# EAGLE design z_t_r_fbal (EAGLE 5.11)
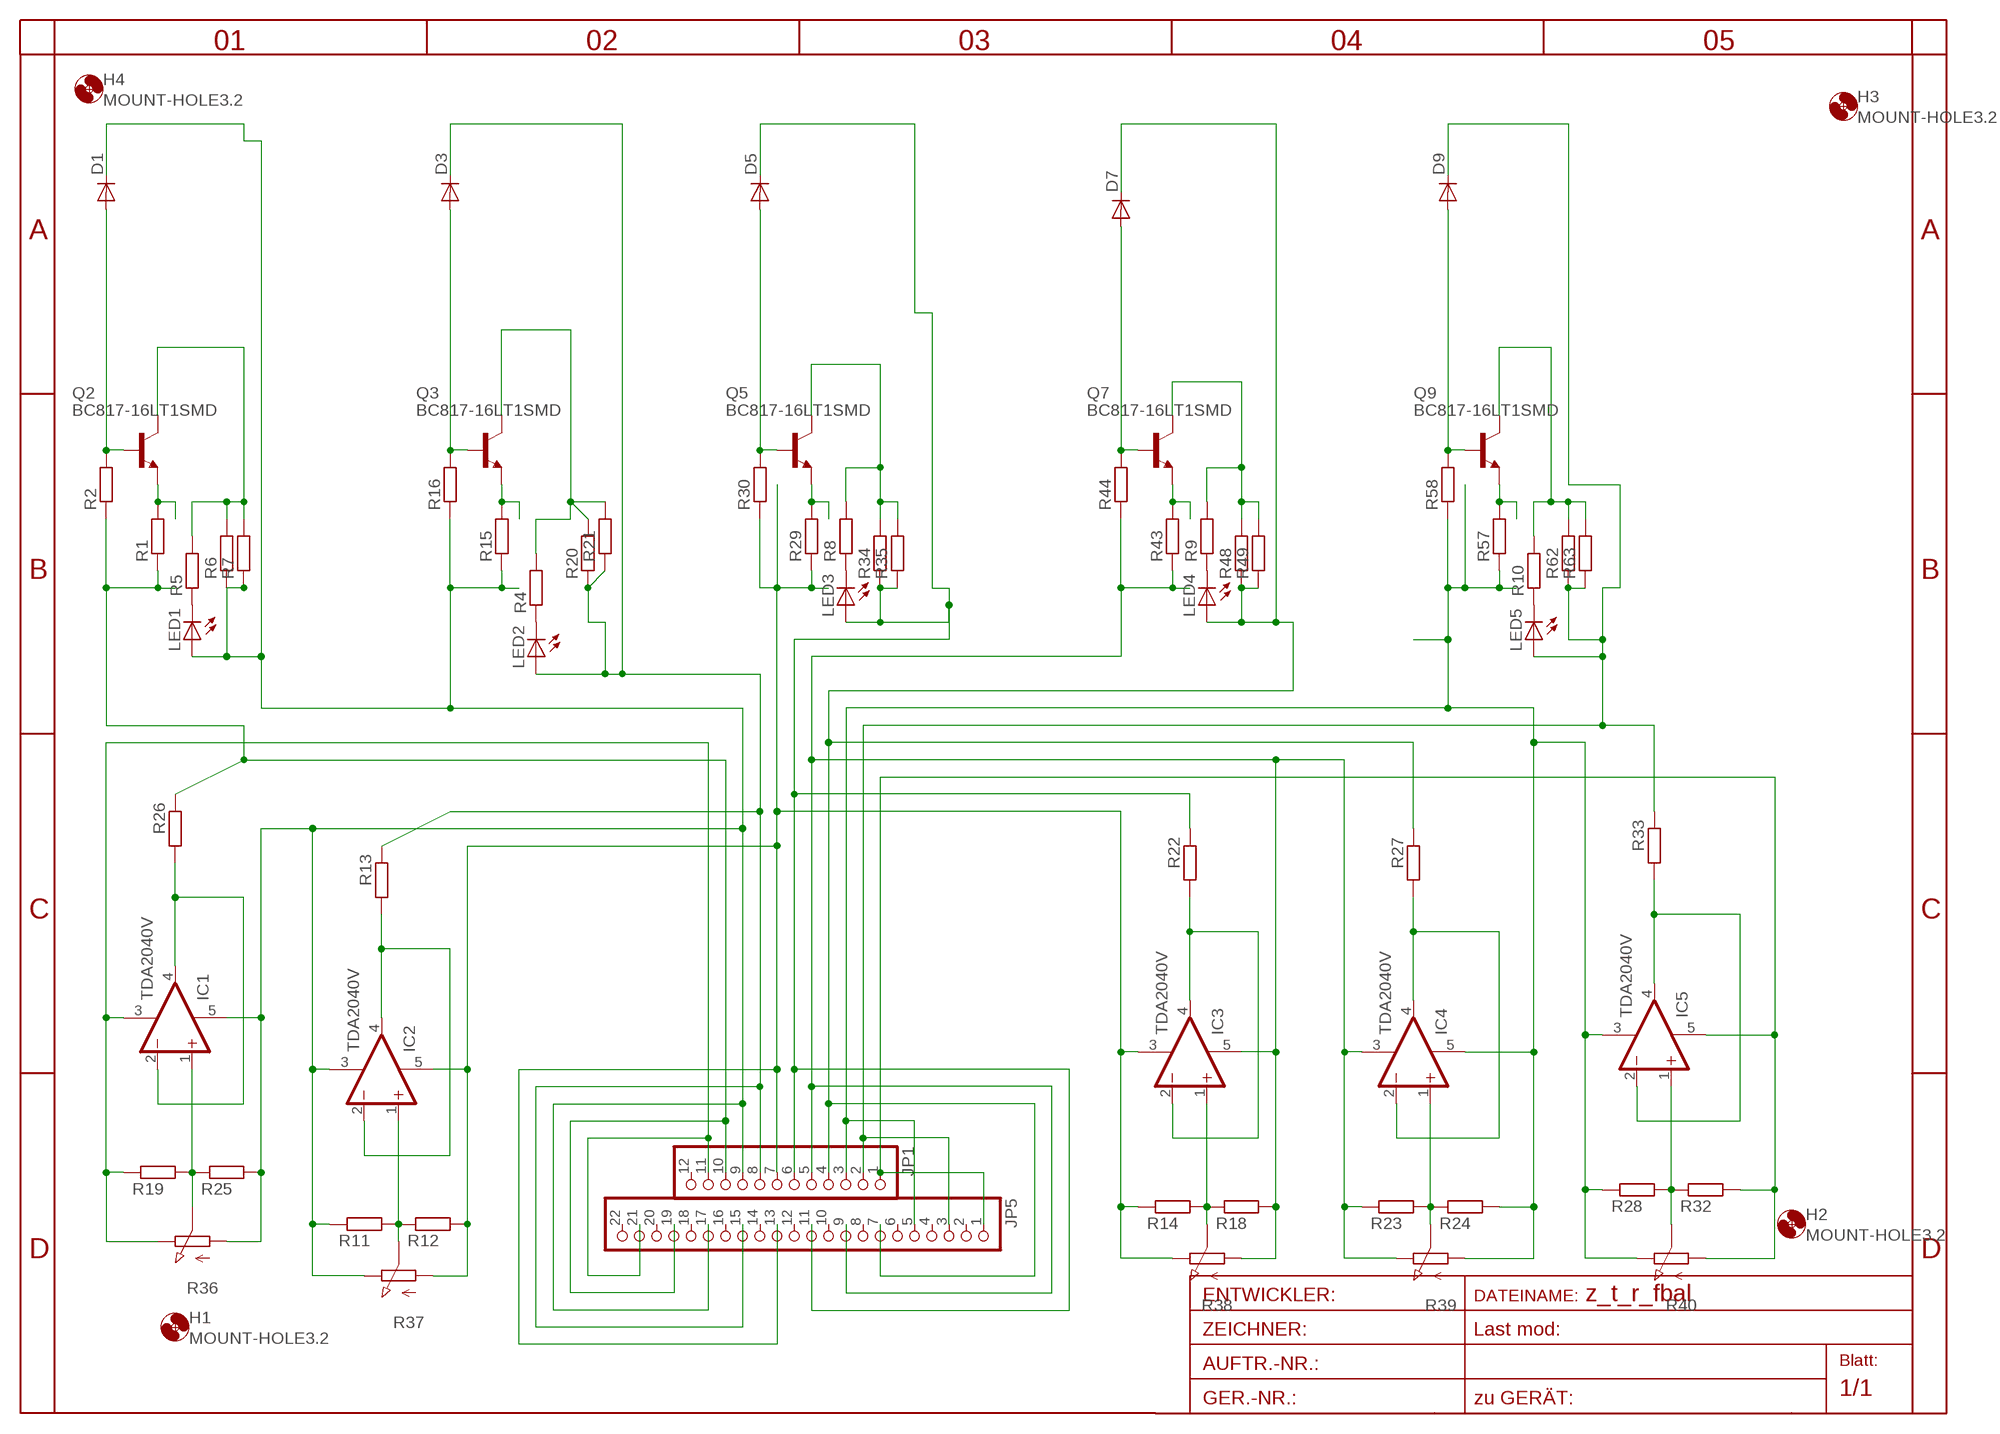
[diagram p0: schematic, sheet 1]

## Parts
D1  DIODE-MINIMELF  [MINIMELF]
D3  DIODE-MINIMELF  [MINIMELF]
D5  DIODE-MINIMELF  [MINIMELF]
D7  DIODE-MINIMELF  [MINIMELF]
D9  DIODE-MINIMELF  [MINIMELF]
H1  MOUNT-HOLE3.2  [3,2]
H2  MOUNT-HOLE3.2  [3,2]
H3  MOUNT-HOLE3.2  [3,2]
H4  MOUNT-HOLE3.2  [3,2]
IC1  TDA2040V  [CB360]
IC2  TDA2040V  [CB360]
IC3  TDA2040V  [CB360]
IC4  TDA2040V  [CB360]
IC5  TDA2040V  [CB360]
JP1  PINHD-1X12  [1X12]
JP5  PINHD-1X22  [1X22]
LED1  LEDCHIPLED_1206  [CHIPLED_1206]
LED2  LEDCHIPLED_1206  [CHIPLED_1206]
LED3  LEDCHIPLED_1206  [CHIPLED_1206]
LED4  LEDCHIPLED_1206  [CHIPLED_1206]
LED5  LEDCHIPLED_1206  [CHIPLED_1206]
Q2  BC817-16LT1SMD  [SOT23-BEC]
Q3  BC817-16LT1SMD  [SOT23-BEC]
Q5  BC817-16LT1SMD  [SOT23-BEC]
Q7  BC817-16LT1SMD  [SOT23-BEC]
Q9  BC817-16LT1SMD  [SOT23-BEC]
R1  R-EU_R1206  [R1206]
R2  R-EU_R0805  [R0805]
R4  R-EU_R1206  [R1206]
R5  R-EU_R1206  [R1206]
R6  R-EU_R3225  [R3225]
R7  R-EU_R3225  [R3225]
R8  R-EU_R1206  [R1206]
R9  R-EU_R1206  [R1206]
R10  R-EU_R1206  [R1206]
R11  R-EU_0204/5  [0204/5]
R12  R-EU_0204/5  [0204/5]
R13  R-EU_0309/10  [0309/10]
R14  R-EU_0204/5  [0204/5]
R15  R-EU_R1206  [R1206]
R16  R-EU_R0805  [R0805]
R18  R-EU_0204/5  [0204/5]
R19  R-EU_0204/5  [0204/5]
R20  R-EU_R3225  [R3225]
R21  R-EU_R3225  [R3225]
R22  R-EU_0309/10  [0309/10]
R23  R-EU_0204/5  [0204/5]
R24  R-EU_0204/5  [0204/5]
R25  R-EU_0204/5  [0204/5]
R26  R-EU_0309/10  [0309/10]
R27  R-EU_0309/10  [0309/10]
R28  R-EU_0204/5  [0204/5]
R29  R-EU_R1206  [R1206]
R30  R-EU_R0805  [R0805]
R32  R-EU_0204/5  [0204/5]
R33  R-EU_0309/10  [0309/10]
R34  R-EU_R3225  [R3225]
R35  R-EU_R3225  [R3225]
R36  PC25  [PC25]
R37  PC25  [PC25]
R38  PC25  [PC25]
R39  PC25  [PC25]
R40  PC25  [PC25]
R43  R-EU_R1206  [R1206]
R44  R-EU_R0805  [R0805]
R48  R-EU_R3225  [R3225]
R49  R-EU_R3225  [R3225]
R57  R-EU_R1206  [R1206]
R58  R-EU_R0805  [R0805]
R62  R-EU_R3225  [R3225]
R63  R-EU_R3225  [R3225]

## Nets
B1: JP1.10 JP5.19 R1.1 R2.1 R26.1
B2: D1.C IC1.5(V+) IC2.3(V-) JP1.9 JP5.17 LED1.A R6.1 R7.1 R11.1 R15.1 R16.1 R25.2 R36.A R37.E
B3: D3.C JP1.8 JP5.15 LED2.A R13.1 R20.1 R21.1
B4: IC2.5(V+) IC3.3(V-) JP1.7 JP5.13 R12.2 R14.1 R29.1 R30.1 R37.A R38.E
B5: D5.C JP1.6 JP5.11 LED3.A R22.1 R34.1 R35.1
B6: IC3.5(V+) IC4.3(V-) JP1.5 JP5.9 R18.2 R23.1 R38.A R39.E R43.1 R44.1
B7: D7.C JP1.4 JP5.7 LED4.A R27.1 R48.1 R49.1
B8: IC4.5(V+) IC5.3(V-) JP1.3 JP5.5 R24.2 R28.1 R39.A R40.E R57.1 R58.1
B9: D9.C JP1.2 JP5.3 LED5.A R33.1 R62.1 R63.1
B10: IC5.5(V+) JP1.1 JP5.1 R32.2 R40.A
B-: IC1.3(V-) JP1.11 JP5.21 R19.1 R36.E
D0: D1.A Q2.B R2.2
D2: D3.A Q3.B R16.2
D4: D5.A Q5.B R30.2
D6: D7.A Q7.B R44.2
D8: D9.A Q9.B R58.2
INV_1: IC1.2(-IN) IC1.4(OUT) R26.2
INV_2: IC2.2(-IN) IC2.4(OUT) R13.2
INV_3: IC3.2(-IN) IC3.4(OUT) R22.2
INV_4: IC4.2(-IN) IC4.4(OUT) R27.2
INV_5: IC5.2(-IN) IC5.4(OUT) R33.2
N$1: Q2.C R5.2 R6.2 R7.2
N$2: Q2.E R1.2
N$3: Q3.C R4.2 R20.2 R21.2
N$4: LED2.C R4.1
N$7: Q5.C R8.2 R34.2 R35.2
N$8: LED3.C R8.1
N$9: Q7.C R9.2 R48.2 R49.2
N$11: LED4.C R9.1
N$13: Q9.C R10.2 R62.2 R63.2
N$14: Q7.E R43.2
N$15: LED5.C R10.1
N$17: LED1.C R5.1
N$18: Q9.E R57.2
N$23: Q5.E R29.2
N$24: Q3.E R15.2
NON_I1: IC1.1(+IN) R19.2 R25.1 R36.S
NON_I2: IC2.1(+IN) R11.2 R12.1 R37.S
NON_I3: IC3.1(+IN) R14.2 R18.1 R38.S
NON_I4: IC4.1(+IN) R23.2 R24.1 R39.S
NON_I5: IC5.1(+IN) R28.2 R32.1 R40.S
Unconnected: JP1.12 JP5.2 JP5.4 JP5.6 JP5.8 JP5.10 JP5.12 JP5.14 JP5.16 JP5.18 JP5.20 JP5.22

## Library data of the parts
D1 D3 D5 D7 D9 = diode-1:DIODE-: DIODE
H1-H4 = holes:MOUNT-HOLE: MOUNTING HOLE with drill center marker
IC1-IC5 = linear:TDA2040: Power OP AMP
JP1 = pinhead:PINHD-1X12: PIN HEADER
JP5 = pinhead:PINHD-1X22: PIN HEADER
LED1-LED5 = led:LED: LED
Q2 Q3 Q5 Q7 Q9 = transistor-npn:BC817*: NPN Transistor
R1 R2 R4-R16 R18-R30 R32-R35 R43 R44 R48 R49 R57 R58 R62 R63 = rcl-2:R-EU_: RESISTOR, European symbol
R36-R40 = pot-vitrohm:PC25: VITROHM POTENTIOMETER

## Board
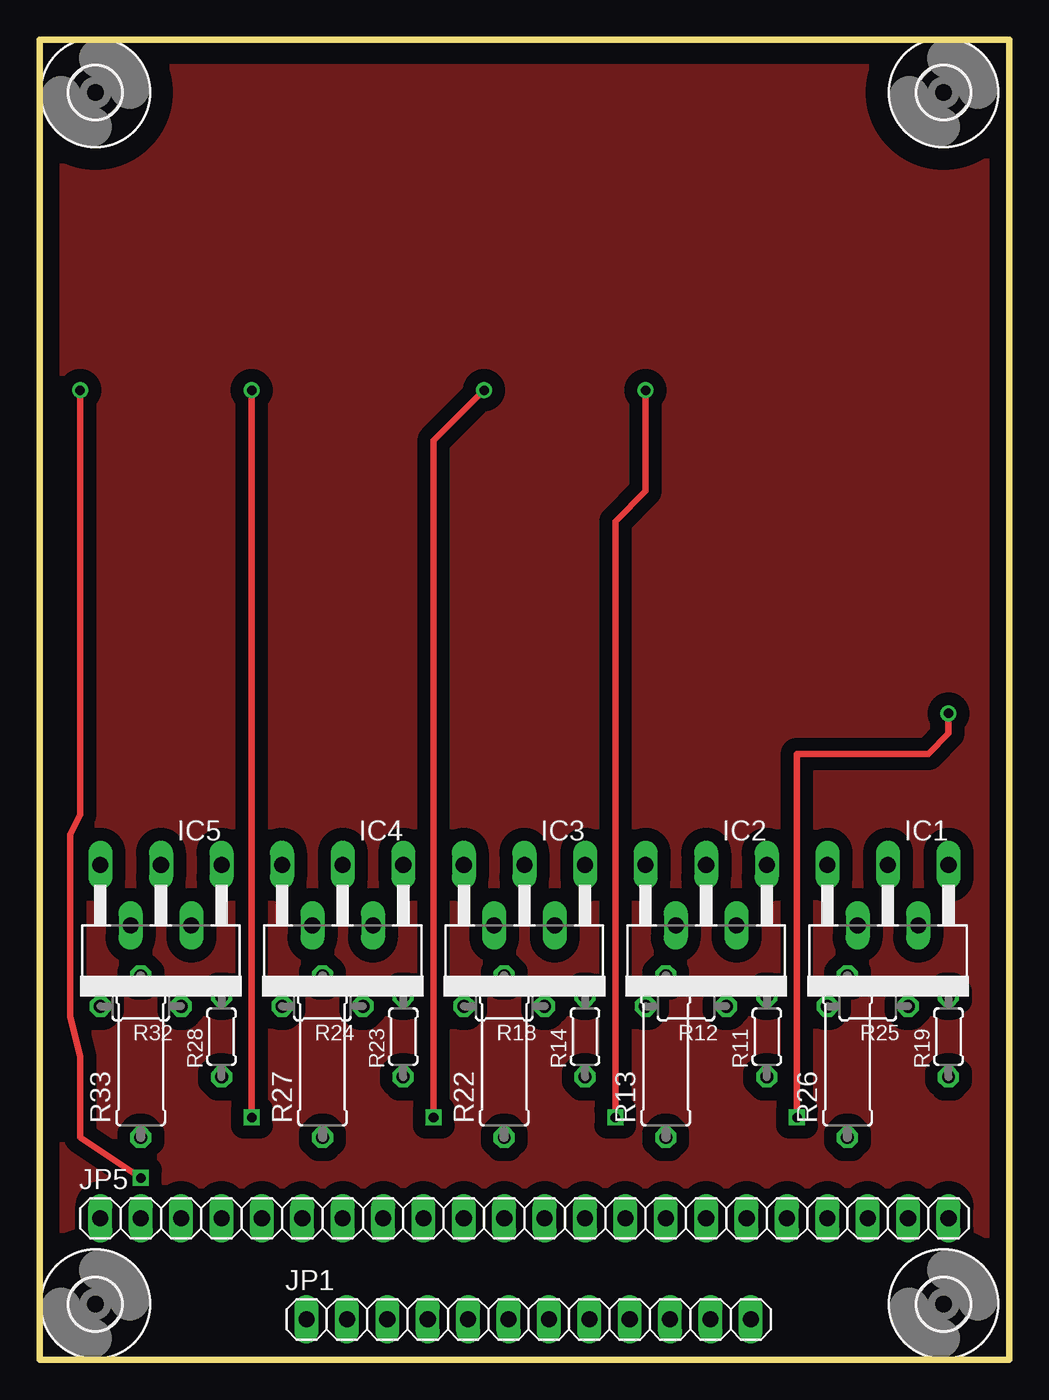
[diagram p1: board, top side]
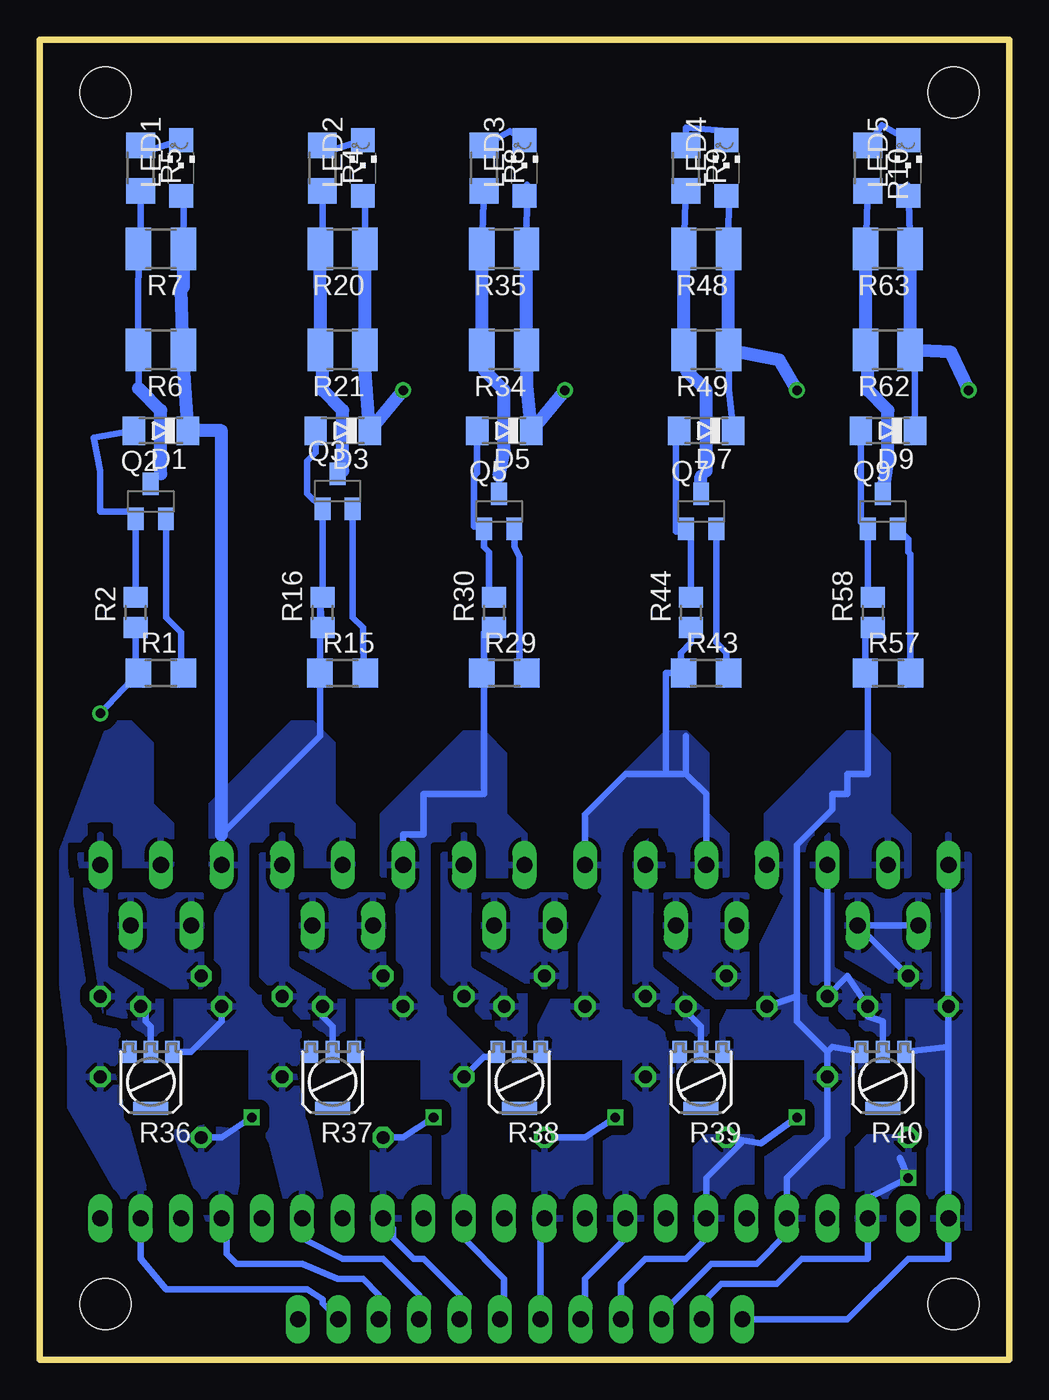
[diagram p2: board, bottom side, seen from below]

Size 60.96 x 83 mm. Coordinates in mm from the lower left corner, seen from the top.
Outline: 0,0 60.96,0 60.96,83 0,83 0,0
Copper layers (1*16): Top 0.035mm / dielectric 1.5mm / Bottom 0.035mm
Design rules "default": minimum track width 10mil, minimum drill 24mil, track to track 8mil, track to pad 8mil, pad to pad 8mil, via to via 8mil, smd to smd 8mil, copper to edge 40mil, drill to drill 8mil, minimum pad ring 10mil, minimum via ring 8mil, stop-mask expansion 4mil, vias tented up to drill 0mil, thermal gap 10mil

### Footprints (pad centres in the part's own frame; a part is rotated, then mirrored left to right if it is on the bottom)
MINIMELF = smd 1.4 x 1.8: A 1.7,0; C -1.7,0
3,2 = hole 3.2: 0,0
CB360 = drill 1.016 long: 1 -3.81,-8.255; 2 -1.905,-4.445; 3 0,-8.255; 4 1.905,-4.445; 5 3.81,-8.255
1X12 = drill 1.016 long: 1 -13.97,0; 2 -11.43,0; 3 -8.89,0; 4 -6.35,0; 5 -3.81,0; 6 -1.27,0; 7 1.27,0; 8 3.81,0; 9 6.35,0; 10 8.89,0; 11 11.43,0; 12 13.97,0
1X22 = drill 1.016 long: 1 -26.67,0; 2 -24.13,0; 3 -21.59,0; 4 -19.05,0; 5 -16.51,0; 6 -13.97,0; 7 -11.43,0; 8 -8.89,0; 9 -6.35,0; 10 -3.81,0; 11 -1.27,0; 12 1.27,0; 13 3.81,0; 14 6.35,0; 15 8.89,0; 16 11.43,0; 17 13.97,0; 18 16.51,0; 19 19.05,0; 20 21.59,0; 21 24.13,0; 22 26.67,0
CHIPLED_1206 = smd 1.5 x 1.5: A 0,-1.75; C 0,1.75
SOT23-BEC = smd 1 x 1.4: B -0.95,-1.1; C 0,1.1; E 0.95,-1.1
R1206 = smd 1.6 x 1.803: 1 -1.422,0; 2 1.422,0
R0805 = smd 1.3 x 1.5: 1 -0.95,0; 2 0.95,0
R3225 = smd 1.6 x 2.7: 1 -1.4,0; 2 1.4,0
0204/5 = drill 0.813 octagon: 1 -2.54,0; 2 2.54,0
0309/10 = drill 0.813 octagon: 1 -5.08,0; 2 5.08,0
PC25 = smd 2.2 x 0.8: 4 0,1.65 | smd 0.9 x 1.4: A -1.35,-1.9; E 1.35,-1.9; S 0,-1.9

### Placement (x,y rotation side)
D1  53.34,58.42 180 bottom
D3  41.91,58.42 180 bottom
D5  31.75,58.42 180 bottom
D7  19.05,58.42 180 bottom
D9  7.62,58.42 180 bottom
H1  3.49,79.69 0 top
H2  56.83,79.69 0 top
H3  3.49,3.49 0 top
H4  56.83,3.49 0 top
IC1  53.34,22.86 180 top
IC2  41.91,22.86 180 top
IC3  30.48,22.86 180 top
IC4  19.05,22.86 180 top
IC5  7.62,22.86 180 top
JP1  30.75,2.54 0 top
JP5  30.48,8.89 0 top
LED1  52.07,74.93 0 bottom
LED2  40.64,74.93 0 bottom
LED3  30.48,74.93 0 bottom
LED4  17.78,74.93 0 bottom
LED5  6.35,74.93 0 bottom
Q2  53.98,53.98 0 bottom
Q3  42.23,54.61 0 bottom
Q5  32.07,53.34 0 bottom
Q7  19.37,53.34 0 bottom
Q9  7.94,53.34 0 bottom
R1  53.34,43.18 0 bottom
R2  54.93,46.99 90 bottom
R4  43.18,74.93 270 bottom
R5  54.61,74.93 270 bottom
R6  53.34,63.5 180 bottom
R7  53.34,69.85 180 bottom
R8  33.02,74.93 270 bottom
R9  20.32,74.93 270 bottom
R10  8.89,74.93 270 bottom
R11  45.72,20.32 90 top
R12  40.64,22.23 180 top
R13  39.37,19.05 90 top
R14  34.29,20.32 90 top
R15  41.91,43.18 0 bottom
R16  43.18,46.99 90 bottom
R18  29.21,22.23 180 top
R19  57.15,20.32 90 top
R20  41.91,69.85 180 bottom
R21  41.91,63.5 180 bottom
R22  29.21,19.05 90 top
R23  22.86,20.32 90 top
R24  17.78,22.23 180 top
R25  52.07,22.23 180 top
R26  50.8,19.05 90 top
R27  17.78,19.05 90 top
R28  11.43,20.32 90 top
R29  31.75,43.18 0 bottom
R30  32.38,46.99 90 bottom
R32  6.35,22.23 180 top
R33  6.35,19.05 90 top
R34  31.75,63.5 180 bottom
R35  31.75,69.85 180 bottom
R36  53.98,17.46 180 bottom
R37  42.55,17.46 180 bottom
R38  30.8,17.46 180 bottom
R39  19.37,17.46 180 bottom
R40  7.94,17.46 180 bottom
R43  19.05,43.18 0 bottom
R44  20,46.99 90 bottom
R48  19.05,69.85 180 bottom
R49  19.05,63.5 180 bottom
R57  7.62,43.18 0 bottom
R58  8.57,46.99 90 bottom
R62  7.62,63.5 180 bottom
R63  7.62,69.85 180 bottom

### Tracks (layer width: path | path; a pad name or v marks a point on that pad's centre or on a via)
B1  (via drill 0.6)
  Top 0.406: v47.62,15.24 47.62,38.1 55.88,38.1 57.15,39.37 v57.15,40.64
  Bottom 0.406: JP1.10 39.64,4.08 40.64,5.08 42.23,5.08 44.45,6.03 48.58,6.03 49.21,6.67 49.21,8.57 JP5.19 | R26.1 49.53,13.97 v47.62,15.24 | v57.15,40.64 R1.1 54.93,43.35 R2.1
  pour Bottom (isolate 0.61): 48.58,14.29 50.48,14.61 52.39,14.29 50.16,8.26 49.85,7.94 49.21,7.94 48.58,11.11
B2
  Bottom 0.406: JP1.9 37.1,4.08 39.37,6.35 41.91,6.35 44.45,7.62 JP5.17 44.45,10.16 | 52.07,67.31 51.92,67.46 | 51.92,62.51 R6.1 | R36.A 51.44,19.36 49.53,21.27 R25.2 | IC1.5 49.53,33.02 43.33,39.22 R15.1 43.33,47.48 R16.1 | LED1.A 51.92,72.61 R7.1
  Bottom 0.813: 51.92,67.46 R7.1 | R6.1 52.07,67.31 | 51.92,62.51 D1.C 49.53,58.42 49.53,33.02
  pour Bottom (isolate 0.61, rank 3): 45.4,9.84 46.35,13.65 47.62,15.88 47.62,19.68 53.98,19.68 48.9,29.84 50.16,31.11 50.16,34.92 45.09,40.01 43.81,40.01 42.55,38.73 42.55,34.92 41.27,33.66 41.27,31.11 45.09,31.11 46.35,29.84 46.35,22.23 43.81,19.68 45.09,18.41 43.18,9.84
B3  (via drill 0.6)
  Top 0.406: v36.2,15.24 36.2,52.7 38.1,54.61 v38.1,60.96
  Bottom 0.406: JP1.8 34.56,4.08 36.83,6.35 37.47,6.35 38.73,7.62 38.73,8.26 JP5.15 | R13.1 38.1,13.97 v36.2,15.24 | LED2.A 40.49,72.61 R20.1 | 40.64,62.23 40.49,62.23 R21.1
  Bottom 0.813: R21.1 R20.1 | v38.1,60.96 D3.C 40.49,62.23
  pour Bottom (isolate 0.61): 36.51,13.97 39.37,13.97 40.01,13.34 40.01,8.26 39.69,7.94 39.05,7.94 36.51,10.79
B4
  Bottom 0.406: JP5.13 34.29,7.62 31.75,5.08 31.75,2.81 JP1.7 | R14.1 33.02,19.05 32.46,19.05 R38.E | 33.02,43.18 R29.1 | 33.02,43.18 33.02,45.72 32.38,45.72 R30.1 | 33.02,43.18 33.02,35.56 36.83,35.56 36.83,33.02 38.1,33.02 IC2.5
  pour Bottom (isolate 0.61, rank 3): 35.56,8.89 38.1,8.89 39.37,10.16 39.37,12.7 36.83,15.24 36.83,19.05 43.18,19.05 38.1,29.21 39.37,30.48 39.37,34.29 34.29,39.37 33.02,39.37 31.75,38.1 31.75,34.29 30.48,33.02 30.48,30.48 34.29,30.48 35.56,29.21 35.56,21.59 33.02,19.05 34.29,17.78 34.29,10.16
B5  (via drill 0.6)
  Top 0.406: v24.77,15.24 24.77,57.78 v27.94,60.96
  Bottom 0.406: JP1.6 29.48,8.62 JP5.11 | R22.1 26.67,13.97 v24.77,15.24 | LED3.A 30.33,73.88 R35.1
  Bottom 0.813: R35.1 R34.1 30.33,61.24 D5.C v27.94,60.96
  pour Bottom (isolate 0.61): 26.35,13.97 29.21,13.97 29.84,13.34 29.84,8.26 29.53,7.94 28.89,7.94 26.35,10.79
B6
  Bottom 0.406: R44.1 20,45.09 20.64,44.45 20.64,43.35 R43.1 21.59,43.18 21.59,36.83 | JP5.9 24.13,7.62 26.67,5.08 26.67,2.81 JP1.5 | IC4.3 19.05,35.56 20.32,36.83 | 20.32,36.83 20.32,39.22 | IC3.5 26.67,34.29 24.13,36.83 21.59,36.83 | 20.32,36.83 21.59,36.83
  pour Bottom (isolate 0.61, rank 3): 22.86,8.89 25.4,8.89 26.67,10.16 26.67,12.7 24.13,15.24 24.13,19.05 30.48,19.05 25.4,29.21 26.67,30.48 26.67,34.29 21.59,39.37 20.32,39.37 19.05,38.1 19.05,34.29 17.78,33.02 17.78,30.48 21.59,30.48 22.86,29.21 22.86,21.59 20.32,19.05 21.59,17.78 21.59,10.16
B7  (via drill 0.6)
  Top 0.406: v13.34,15.24 v13.34,60.96
  Bottom 0.406: JP1.4 24.4,4.81 22.86,6.35 20.32,6.35 19.05,7.62 JP5.7 19.05,11.43 16.88,13.6 R27.1 15.61,13.6 v13.34,15.24 | R48.1 17.63,73.73 LED4.A | D7.C 17.63,60.96 R49.1
  Bottom 0.813: R48.1 R49.1 14.45,62.87 v13.34,60.96
  pour Bottom (isolate 0.61): 16.19,13.97 19.05,13.97 19.68,13.34 19.68,8.26 19.37,7.94 18.73,7.94 16.19,10.79
B8
  Bottom 0.406: R58.1 9.04,46.52 R57.1 8.89,43.18 8.89,36.83 10.16,36.83 10.16,35.56 11.11,35.56 11.11,34.61 13.34,32.38 13.34,22.86 | 11.43,19.37 R28.1 11.43,13.97 13.97,11.43 JP5.5 13.97,7.94 15.88,6.03 18.73,6.03 21.59,3.17 21.59,2.81 JP1.3 | 11.43,19.37 13.34,21.27 13.34,22.86 | 13.34,22.86 R24.2 | R40.E 11.12,19.68 11.43,19.37
  pour Bottom (isolate 0.61, rank 3): 11.43,8.89 13.97,8.89 15.24,10.16 15.24,12.7 12.7,15.24 12.7,19.05 19.05,19.05 13.97,29.21 15.24,30.48 15.24,34.29 10.16,39.37 8.89,39.37 7.62,38.1 7.62,34.29 6.35,33.02 6.35,30.48 10.16,30.48 11.43,29.21 11.43,21.59 8.89,19.05 10.16,17.78 10.16,10.16
B9  (via drill 0.6)
  Top 0.406: v2.54,60.96 2.54,34.29 1.91,33.02 1.91,21.59 2.54,19.05 2.54,13.97 v6.35,11.43
  Bottom 0.406: 6.35,73.66 R63.1 6.35,73.81 LED5.A | 6.88,12.7 v6.35,11.43 8.89,10.16 JP5.3 8.89,6.35 13.02,6.35 14.61,4.76 18.1,4.76 19.37,3.49 19.37,2.59 JP1.2 | D9.C 5.92,64.49 R62.1
  Bottom 0.813: R63.1 R62.1 3.66,63.35 v2.54,60.96
  pour Bottom (isolate 0.61): 6.03,13.97 8.89,13.97 9.53,13.34 9.53,8.26 9.21,7.94 8.57,7.94 6.03,10.79
B10
  Bottom 0.406: IC5.5 R32.2 3.81,19.05 | 3.81,19.05 JP5.1 3.81,6.35 6.35,6.35 10.16,2.54 JP1.1 | R40.A 3.81,19.68 3.81,19.05
  pour Bottom (isolate 0.61, rank 2): 3.81,33.02 2.54,31.75 2.54,6.35 5.08,6.35 5.08,17.78 6.35,19.05 6.35,22.86 5.08,22.86
B-
  Bottom 0.406: JP5.21 54.61,6.35 53.02,4.45 44.13,4.45 43.18,3.81 43.18,3.54 JP1.11
  pour Bottom (isolate 0.61, rank 3): 55.24,9.21 59.05,15.88 59.05,19.68 60.33,29.84 56.52,40.01 55.24,40.01 53.98,38.73 53.98,34.92 52.7,33.66 52.7,31.11 56.52,31.11 57.78,29.84 57.78,22.23 55.24,19.68 56.52,18.41 53.98,9.21
D0
  Bottom 0.406: R2.2 Q2.B 55.39,53.34 57.15,53.34 57.15,55.88 57.58,57.99 D1.A
D2
  Bottom 0.406: D3.A 43.61,57.04 44.13,56.52 44.13,54.47 Q3.B R16.2
D4
  Bottom 0.406: D5.A 33.45,55.77 33.66,55.56 33.66,52.39 33.16,52.39 Q5.B 33.02,51.12 32.7,50.8 32.7,48.58 R30.2
D6
  Bottom 0.406: D7.A 20.95,58.42 20.95,52.07 20.32,52.07 Q7.B 20,52.24 R44.2
D8
  Bottom 0.406: R58.2 8.89,48.58 Q9.B 9.32,52.67 D9.A
INV_1
  pour Bottom (isolate 0.61): 50.8,29.21 55.88,29.21 55.88,25.4 52.7,23.5 50.8,23.5
INV_2
  pour Bottom (isolate 0.61): 39.37,29.21 44.45,29.21 44.45,25.4 41.27,23.5 39.37,23.5
INV_3
  pour Bottom (isolate 0.61): 27.94,29.21 33.02,29.21 33.02,25.4 29.84,23.5 27.94,23.5
INV_4
  pour Bottom (isolate 0.61): 16.51,29.21 21.59,29.21 21.59,25.4 18.41,22.86 16.51,22.86
INV_5
  Bottom 0.406: IC5.4 IC5.2 R33.2
  pour Bottom (isolate 0.61): 5.08,29.21 10.16,29.21 10.16,25.4 6.99,23.5 5.08,23.5
N$1
  Bottom 0.406: Q2.C 53.34,55.71 | R5.2 54.61,71.27 R7.2 54.76,66.19 54.76,63.52 R6.2 54.74,61.09
  Bottom 0.813: 53.34,55.71 53.34,59.69 54.74,61.09
N$2
  Bottom 0.406: Q2.E 53.02,46.67 52.07,45.72 52.07,43.33 R1.2
N$3
  Bottom 0.406: 43.33,67.46 43.18,67.31 43.31,67.18 | 41.91,55.88 42.06,55.88 Q3.C | R4.2 43.18,71.27 R20.2 | 43.18,63.37 R21.2
  Bottom 0.813: 43.33,67.46 R20.2 | 41.91,55.88 41.91,59.69 43.18,60.96 43.18,63.37 | R21.2 43.31,67.18
N$4
  Bottom 0.406: LED2.C 42.81,75.98 R4.1
N$7
  Bottom 0.406: Q5.C 32.07,55.56 | 33.02,63.5 33.02,65.89 R34.2 33.02,63.37 33.02,62.23 | R8.2 33.02,73.81 R35.2
  Bottom 0.813: R34.2 R35.2 | 32.07,55.56 31.75,57.15 31.75,60.96 33.02,62.23
N$8
  Bottom 0.406: LED3.C 31.38,77.25 R8.1
N$9
  Bottom 0.406: R9.2 20.32,73.81 R48.2 | 19.37,55.56 19.05,55.88 | 20.32,62.23 20.32,63.37 R49.2
  Bottom 0.813: R49.2 R48.2 | Q7.C 19.37,55.56 | 19.05,55.88 19.05,60.96 20.32,62.23
N$11
  Bottom 0.406: LED4.C 17.56,77.25 20.32,77.47 R9.1
N$13
  Bottom 0.406: 8.89,65.89 R62.2 8.89,63.37 | R10.2 8.89,73.81 R63.2
  Bottom 0.813: Q9.C 7.62,56.52 7.62,59.69 8.89,60.96 8.89,63.37 | R62.2 R63.2
N$14
  Bottom 0.406: Q7.E 18.42,45.09 17.78,44.45 17.78,43.33 R43.2
N$15
  Bottom 0.406: R10.1 7.99,77.62 LED5.C
N$17
  Bottom 0.406: LED1.C 54.24,75.98 R5.1
N$18
  Bottom 0.406: R57.2 6.2,50.65 6.35,50.8 6.35,51.6 Q9.E
N$22
  pour Top (isolate 0.813, rank 2): 0,81.28 60.96,81.28 60.96,7.62 0,7.62
N$23
  Bottom 0.406: Q5.E 31.12,51.12 30.8,50.48 30.8,43.33 R29.2
N$24
  Bottom 0.406: Q3.E 41.28,46.67 40.64,46.04 40.64,44.6 R15.2
NON_I1
  Bottom 0.406: R36.S 53.98,20.95 54.29,21.27 54.29,21.91 R25.1
  pour Bottom (isolate 0.61, rank 2): 57.15,33.02 58.42,31.75 56.83,21.91 55.56,21.59 53.34,19.68 53.34,24.13 54.29,24.77 56.2,26.67 56.2,28.57
NON_I2
  Bottom 0.406: R12.1 43.18,21.59 42.55,20.95 R37.S
  pour Bottom (isolate 0.61, rank 2): 45.72,33.02 46.99,31.75 46.99,24.13 44.45,21.59 44.13,21.59 41.91,19.68 41.91,24.13 42.86,24.77 44.77,26.67 44.77,28.57
NON_I3
  pour Bottom (isolate 0.61, rank 2): 34.29,33.02 35.56,31.75 35.56,24.13 33.02,21.59 32.7,21.59 30.48,19.68 30.48,24.13 31.43,24.77 33.34,26.67 33.34,28.57
NON_I4
  Bottom 0.406: R24.1 20.32,21.91 19.37,20.95 R39.S
  pour Bottom (isolate 0.61, rank 2): 22.23,33.02 23.5,31.75 23.5,22.86 20.95,21.59 20.64,20.32 19.05,20 19.05,24.45 21.27,26.67 21.27,28.57
NON_I5
  Bottom 0.406: IC5.1 R28.2 10.16,24.13 R32.1 8.89,21.59 7.94,21.27 R40.S
  pour Bottom (isolate 0.61, rank 2): 11.43,33.02 12.7,31.75 12.7,24.13 10.16,21.59 9.84,21.59 7.62,19.68 7.62,24.13 8.57,24.77 10.48,26.67 10.48,28.57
